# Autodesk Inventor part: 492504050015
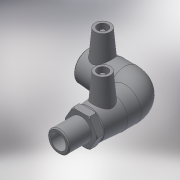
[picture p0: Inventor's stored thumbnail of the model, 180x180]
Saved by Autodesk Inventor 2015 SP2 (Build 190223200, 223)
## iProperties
Created: 2017-06
Part Number: 492504050015
Material: Generic
Description: PLASSON 90° ELBOW MALE TRANSITION 50-1.1/2"
Document SubType Name: Modeling
Designer: KIM
Mass: 298.582 g
Surface Area: 672.549 cm^2
Volume: 298.582 cm^3
Density: 1 g/cm^3
Appearance: Default
Author: KIM
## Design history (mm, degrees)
derived "492504.ipt"
feature "Solid1::492504.ipt"
tag "TaggingFeature1"
body "Solid1"
other parameters: "d2" = 67, "d4" = 36, "d5" = 60.3, "d8" = 168 deg, "d10" = 19.2, "d11" = 6.4, "d29" = 52, "d30" = 15, "d31" = 59.4, "d34" = 5 deg, "d41" = 4, "d42" = 14, "d43" = 0, "d48" = 74.5, "d50" = 42.5, "d51" = 19.2, "d52" = 48, "d54" = 90 deg, "d58" = 48, "d59" = 0, "d61" = 90 deg, "d86" = 3, "d87" = 0, "d93" = 0.1, "d94" = 9, "d95" = 47.803, "d96" = 33.4621, "d97" = 38, "d98" = 36, "d99" = 67, "d100" = 32.4, "d102" = 2.5, "d106" = 0, "L_" = 144, "L_1" = 48, "D_" = 38, "A_" = 52, "d_2" = 12, "L_2" = 36, "D_1" = 67, "R_" = 47.803
